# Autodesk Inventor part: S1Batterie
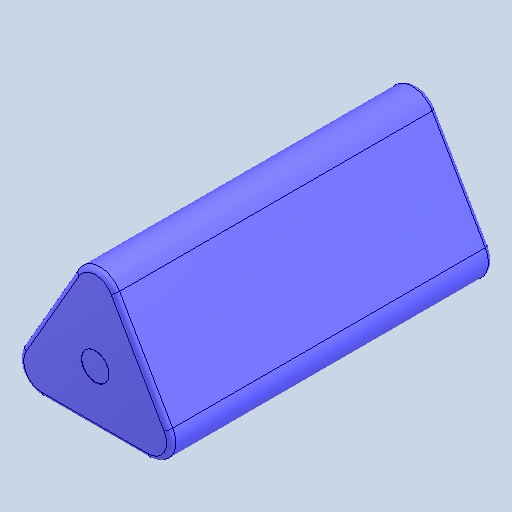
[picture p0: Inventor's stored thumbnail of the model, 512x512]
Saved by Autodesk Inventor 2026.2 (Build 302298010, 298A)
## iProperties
Created: 1601-01
Part Number: S1Batterie
Material: Générique
Document SubType Name: Modeling
Designer: mel
Density: 1 g/cm^3
Appearance: Par défaut
Author: mel
Sending System: SOLIDWORKS 2023
Part Number: Batterie
Last Saved Date: 2025-04-02
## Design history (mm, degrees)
feature "Enlèv. mat.-Extru.1"
node "Solide1"
